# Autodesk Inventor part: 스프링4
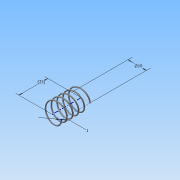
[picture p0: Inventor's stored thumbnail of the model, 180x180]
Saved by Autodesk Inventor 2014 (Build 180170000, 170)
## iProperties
Created: 2015-06
Part Number: 스프링4
Material: 강철, 연강
Document SubType Name: Modeling
Designer: Administrator
Density: 7.86 g/cm^3
Appearance: 강철
Mass: 1.52988 g
Surface Area: 7.87024 cm^2
Volume: 0.194641 cm^3
Author: Administrator
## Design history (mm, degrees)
sketch "스케치1"
  geometry: L1 (0, 0)-(8, 0); L2 (8, 0)-(8, 14.5); L3 (8, 14.5)-(0, 14.5); L4 (0, 14.5)-(0, 0); C1 r 0.5 at (8, 0)
  constraints: 8 end point, 2 parallel, 1 centre point, 1 coincident, 1 horizontal, 1 perpendicular
  dimensions: "d0" = 14.5 distance of L3.end L1.start (derived); "d1" = 16 diameter of L2 L4; "d2" = 1 diameter of C1
feature "코일1" sketch "스케치1" pitch "d3" = 10; turns "d5" = 5; dims "d4" = 14.5 (= d0), "d6" = 0, angle "d7" = 90 deg, angle "d8" = 90 deg, "d9" = 0, "d10" = 0
sketch "스케치2"
  geometry: L1 (-8.5, 0)-(-7.5, 0) reference; 1 further point
  constraints: 1 horizontal alignment
extrude "돌출1" cut sketch "스케치2" stored distance "d11" = 10; taper "d12" = 0 deg
node "작업 평면1"
sketch "스케치3"
  geometry: L1 (-7.5, 0)-(-8.5, 0) reference; 1 further point
  constraints: 1 horizontal alignment
extrude "돌출2" cut sketch "스케치3" stored distance "d14" = 10; taper "d15" = 0 deg
node "솔리드1"
node "절단 모서리 투영1"
node "절단 모서리 투영2"
other parameters: "d13" = 14.5 (= d0)
